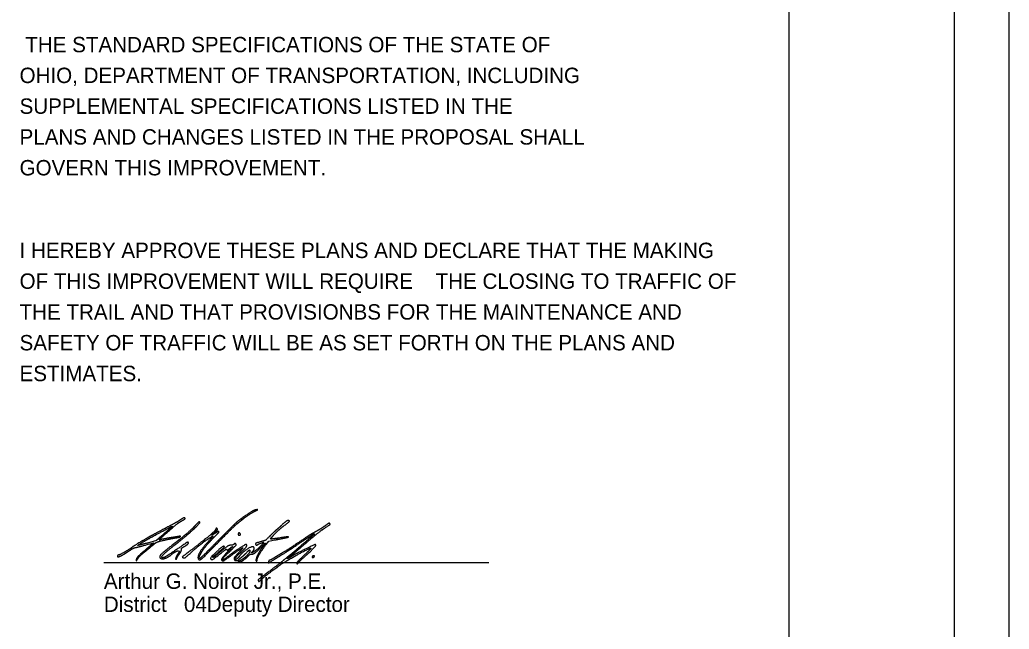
# Model space of a CAD drawing. Extents: x 0 to 34, y 0 to 22.
# Drawn here: x 25 to 34, y 5.54 to 11.09 of the extents above; entities that cross this region are included whole.
import ezdxf

# ---------------------------------------------------------------- set-up
doc = ezdxf.new("R2010")
doc.units = 0
for name, color, linetype in [('GM_X_Adjacent_County', 7, 'Continuous'), ('GM_X_County', 7, 'Continuous'), ('GM_X_Section', 7, 'Continuous'), ('GM_X_Township', 7, 'Continuous')]:
    doc.layers.add(name, color=color, linetype=linetype)

msp = doc.modelspace()

# ---------------------------------------------------------------- linework, layer by layer
at = {"layer": 'GM_X_Adjacent_County'}
for points in [[(26.2935, 6.3944), (26.2439, 6.3503), (26.1624, 6.3283)], [(26.7672, 6.4101), (26.7469, 6.3986), (26.7751, 6.4249)], [(27.2428, 6.3143), (27.2658, 6.3447), (27.3219, 6.3561)], [(27.2968, 6.3642), (27.2808, 6.3622), (27.2948, 6.38)], [(26.4457, 6.2567), (26.4563, 6.2553), (26.4396, 6.2295)]]:
    msp.add_lwpolyline(points, dxfattribs=at)
for points in [[(27.1637, 6.6317), (27.1424, 6.6325), (27.0858, 6.6008), (27.0143, 6.5481)], [(27.0362, 6.5502), (27.0535, 6.5648), (27.1287, 6.6126), (27.1491, 6.6219)], [(27.1491, 6.6219), (27.1608, 6.6272), (27.1673, 6.6316), (27.1637, 6.6317)], [(26.1849, 6.3732), (26.2619, 6.416), (26.3873, 6.4819), (26.3889, 6.4803)], [(26.4616, 6.5381), (26.4443, 6.5265), (26.3934, 6.4978), (26.3483, 6.4743)], [(26.3555, 6.4361), (26.4202, 6.4925), (26.4521, 6.5174), (26.4779, 6.5316)], [(26.3889, 6.4803), (26.3895, 6.4797), (26.3794, 6.4701), (26.3665, 6.4589)], [(26.4991, 6.557), (26.4955, 6.5583), (26.48, 6.5505), (26.4616, 6.5381)], [(26.4779, 6.5316), (26.5032, 6.5455), (26.5095, 6.553), (26.4991, 6.557)], [(26.6012, 6.4909), (26.5759, 6.4639), (26.5201, 6.4125), (26.4915, 6.3901)], [(26.5144, 6.3932), (26.5522, 6.4244), (26.639, 6.5083), (26.639, 6.5137)], [(26.639, 6.5137), (26.639, 6.5245), (26.6243, 6.5156), (26.6012, 6.4909)], [(27.0143, 6.5481), (26.976, 6.5198), (26.9355, 6.4815), (26.8059, 6.3505)], [(26.8219, 6.3499), (26.8944, 6.424), (26.9629, 6.4916), (26.974, 6.5002)], [(26.974, 6.5002), (26.9963, 6.5176), (27.0233, 6.5393), (27.0362, 6.5502)], [(27.2948, 6.38), (27.3196, 6.4115), (27.3688, 6.4583), (27.4102, 6.4897)], [(27.3779, 6.4851), (27.3645, 6.4722), (27.3471, 6.4567), (27.3393, 6.4505)], [(27.4477, 6.5326), (27.4397, 6.5356), (27.409, 6.5148), (27.3779, 6.4851)], [(27.4102, 6.4897), (27.4521, 6.5214), (27.4583, 6.5285), (27.4477, 6.5326)], [(27.8004, 6.4999), (27.7709, 6.4782), (27.7197, 6.4454), (27.6918, 6.4304)], [(27.7791, 6.4668), (27.822, 6.495), (27.8271, 6.5), (27.8202, 6.5068)], [(27.8202, 6.5068), (27.817, 6.51), (27.8115, 6.5081), (27.8004, 6.4999)], [(26.3483, 6.4743), (26.2723, 6.4348), (26.1933, 6.3924), (26.1789, 6.3836)], [(26.2735, 6.3566), (26.265, 6.3538), (26.3006, 6.3884), (26.3555, 6.4361)], [(26.3665, 6.4589), (26.3535, 6.4477), (26.3207, 6.4187), (26.2935, 6.3944)], [(26.3947, 6.2975), (26.4337, 6.3274), (26.4613, 6.3495), (26.5144, 6.3932)], [(26.4573, 6.3902), (26.4531, 6.3889), (26.4312, 6.3851), (26.4088, 6.3818)], [(26.4631, 6.3873), (26.4643, 6.3909), (26.4624, 6.3918), (26.4573, 6.3902)], [(26.4915, 6.3901), (26.4832, 6.3836), (26.4775, 6.3765), (26.4789, 6.3742)], [(26.5571, 6.2398), (26.6082, 6.2867), (26.7482, 6.3917), (26.7596, 6.3917)], [(26.7835, 6.4538), (26.7782, 6.4396), (26.6843, 6.3583), (26.5896, 6.2859)], [(26.7596, 6.3917), (26.7608, 6.3917), (26.7487, 6.3775), (26.7327, 6.3602)], [(26.766, 6.3771), (26.7924, 6.4037), (26.814, 6.4271), (26.814, 6.429)], [(26.794, 6.427), (26.7905, 6.4241), (26.7784, 6.4164), (26.7672, 6.4101)], [(26.7751, 6.4249), (26.7927, 6.4413), (26.8021, 6.4531), (26.8003, 6.4561)], [(26.8003, 6.4561), (26.7958, 6.4633), (26.7865, 6.462), (26.7835, 6.4538)], [(26.814, 6.429), (26.814, 6.4343), (26.8012, 6.4331), (26.794, 6.427)], [(27.0042, 6.415), (26.9968, 6.4224), (26.9891, 6.4187), (26.9891, 6.4078)], [(26.9891, 6.4078), (26.9891, 6.4027), (26.9919, 6.3999), (26.997, 6.3999)], [(26.997, 6.3999), (27.008, 6.3999), (27.0117, 6.4076), (27.0042, 6.415)], [(27.2802, 6.3955), (27.2363, 6.3526), (27.2348, 6.3516), (27.2038, 6.343)], [(27.3393, 6.4505), (27.3314, 6.4443), (27.3049, 6.4195), (27.2802, 6.3955)], [(27.5001, 6.2952), (27.6063, 6.3677), (27.6813, 6.4151), (27.6813, 6.4098)], [(27.6918, 6.4304), (27.652, 6.409), (27.6219, 6.3902), (27.5611, 6.3489)], [(27.6701, 6.3984), (27.664, 6.3936), (27.625, 6.3604), (27.5835, 6.3246)], [(27.6161, 6.3382), (27.6704, 6.3852), (27.7467, 6.4454), (27.7791, 6.4668)], [(27.6813, 6.4098), (27.6813, 6.4084), (27.6762, 6.4032), (27.6701, 6.3984)], [(26.0929, 6.3335), (26.0415, 6.302), (26.034, 6.2971), (26.0178, 6.2847)], [(26.0485, 6.2859), (26.0527, 6.2859), (26.09, 6.295), (26.1313, 6.3062)], [(26.0761, 6.3062), (26.0716, 6.3062), (26.138, 6.3471), (26.1849, 6.3732)], [(26.1624, 6.3283), (26.1176, 6.3162), (26.0788, 6.3062), (26.0761, 6.3062)], [(26.1159, 6.347), (26.1153, 6.347), (26.1049, 6.3409), (26.0929, 6.3335)], [(26.1789, 6.3836), (26.1619, 6.3732), (26.1169, 6.347), (26.1159, 6.347)], [(26.1313, 6.3062), (26.212, 6.3281), (26.2224, 6.33), (26.2094, 6.3202)], [(26.1931, 6.307), (26.1887, 6.3032), (26.1627, 6.2813), (26.1355, 6.2584)], [(26.1896, 6.2902), (26.2095, 6.3072), (26.2312, 6.325), (26.2379, 6.3298)], [(26.2094, 6.3202), (26.205, 6.3168), (26.1976, 6.3109), (26.1931, 6.307)], [(26.2379, 6.3298), (26.2498, 6.3384), (26.3549, 6.3641), (26.43, 6.3767)], [(26.4088, 6.3818), (26.3654, 6.3753), (26.2852, 6.3604), (26.2735, 6.3566)], [(26.411, 6.3256), (26.3062, 6.2453), (26.2639, 6.1993), (26.2847, 6.1882)], [(26.512, 6.327), (26.4934, 6.3126), (26.3394, 6.2096), (26.3267, 6.203)], [(26.4535, 6.3588), (26.4424, 6.35), (26.4233, 6.3351), (26.411, 6.3256)], [(26.43, 6.3767), (26.448, 6.3798), (26.4621, 6.3843), (26.4631, 6.3873)], [(26.4776, 6.3725), (26.4755, 6.3738), (26.4646, 6.3677), (26.4535, 6.3588)], [(26.4789, 6.3742), (26.4803, 6.372), (26.4797, 6.3712), (26.4776, 6.3725)], [(26.4975, 6.2966), (26.5115, 6.3051), (26.5252, 6.3142), (26.528, 6.317)], [(26.528, 6.317), (26.5406, 6.3293), (26.5265, 6.3382), (26.512, 6.327)], [(26.7327, 6.3602), (26.6736, 6.2963), (26.6227, 6.2199), (26.6227, 6.1952)], [(26.6375, 6.176), (26.6479, 6.176), (26.6934, 6.2189), (26.8219, 6.3499)], [(26.8059, 6.3505), (26.7174, 6.2611), (26.6429, 6.188), (26.6402, 6.1881)], [(26.6445, 6.2237), (26.6642, 6.2627), (26.7099, 6.3205), (26.766, 6.3771)], [(26.9248, 6.3085), (26.9042, 6.308), (26.8727, 6.287), (26.792, 6.2197)], [(27.0416, 6.3062), (26.9857, 6.2713), (26.9325, 6.2354), (26.9059, 6.2146)], [(26.9207, 6.2609), (26.9628, 6.3014), (26.9721, 6.3123), (26.9684, 6.3169)], [(26.9476, 6.3157), (26.9434, 6.3119), (26.9332, 6.3086), (26.9248, 6.3085)], [(26.9684, 6.3169), (26.9622, 6.3243), (26.9568, 6.324), (26.9476, 6.3157)], [(27.0279, 6.2577), (27.0513, 6.2792), (27.0663, 6.2979), (27.0664, 6.3054)], [(27.0664, 6.3054), (27.0665, 6.3146), (27.0558, 6.315), (27.0416, 6.3062)], [(27.1067, 6.2255), (27.1215, 6.224), (27.1614, 6.2536), (27.2067, 6.2997)], [(27.22, 6.3332), (27.2229, 6.3304), (27.1522, 6.2617), (27.1357, 6.2513)], [(27.2038, 6.343), (27.158, 6.3304), (27.1436, 6.3237), (27.1464, 6.3164)], [(27.1464, 6.3164), (27.1491, 6.3095), (27.1605, 6.3083), (27.1665, 6.3143)], [(27.2211, 6.3042), (27.1878, 6.2663), (27.1399, 6.1637), (27.1555, 6.1637)], [(27.1601, 6.172), (27.1601, 6.1896), (27.1984, 6.2555), (27.2428, 6.3143)], [(27.1665, 6.3143), (27.1713, 6.319), (27.2178, 6.3355), (27.22, 6.3332)], [(27.2067, 6.2997), (27.2267, 6.3201), (27.2397, 6.3313), (27.2356, 6.3246)], [(27.2356, 6.3246), (27.2316, 6.3178), (27.225, 6.3087), (27.2211, 6.3042)], [(27.3555, 6.3729), (27.332, 6.3692), (27.3056, 6.3653), (27.2968, 6.3642)], [(27.3219, 6.3561), (27.3527, 6.3624), (27.3931, 6.3704), (27.4115, 6.374)], [(27.4451, 6.3834), (27.4451, 6.3864), (27.4284, 6.3844), (27.3555, 6.3729)], [(27.5611, 6.3489), (27.4726, 6.2887), (27.4534, 6.2764), (27.3942, 6.2412)], [(27.4115, 6.374), (27.43, 6.3776), (27.4451, 6.3819), (27.4451, 6.3834)], [(27.5835, 6.3246), (27.5148, 6.2652), (27.4611, 6.2197), (27.4451, 6.2072)], [(27.5632, 6.2929), (27.5867, 6.3129), (27.6105, 6.3333), (27.6161, 6.3382)], [(27.5774, 6.1906), (27.6181, 6.2255), (27.6935, 6.3004), (27.6935, 6.3058)], [(27.6935, 6.3058), (27.6935, 6.3166), (27.6796, 6.3118), (27.605, 6.2754)], [(25.9062, 6.2207), (25.8993, 6.2207), (25.8898, 6.2132), (25.8898, 6.2077)], [(25.8898, 6.2077), (25.8898, 6.2012), (25.9094, 6.2047), (25.928, 6.2146)], [(26.0178, 6.2847), (25.9986, 6.27), (25.9126, 6.2207), (25.9062, 6.2207)], [(25.928, 6.2146), (25.9385, 6.2201), (25.9681, 6.2385), (25.9939, 6.2553)], [(25.9939, 6.2553), (26.0198, 6.2721), (26.0443, 6.2859), (26.0485, 6.2859)], [(26.1355, 6.2584), (26.0901, 6.2202), (26.0608, 6.1868), (26.0608, 6.1732)], [(26.0751, 6.1851), (26.0873, 6.2038), (26.1049, 6.2214), (26.1346, 6.2447)], [(26.1346, 6.2447), (26.145, 6.2528), (26.1697, 6.2733), (26.1896, 6.2902)], [(26.2929, 6.2014), (26.2929, 6.2092), (26.3511, 6.2641), (26.3947, 6.2975)], [(26.3033, 6.1841), (26.3158, 6.1841), (26.3572, 6.2041), (26.3784, 6.2204)], [(26.3784, 6.2204), (26.4089, 6.2439), (26.435, 6.258), (26.4457, 6.2567)], [(26.4396, 6.2295), (26.4304, 6.2152), (26.4217, 6.1981), (26.4203, 6.1913)], [(26.4307, 6.1905), (26.4315, 6.1948), (26.4383, 6.2068), (26.4457, 6.2172)], [(26.4457, 6.2172), (26.4642, 6.2431), (26.472, 6.2592), (26.472, 6.2711)], [(26.472, 6.2711), (26.472, 6.2792), (26.4773, 6.2844), (26.4975, 6.2966)], [(26.5896, 6.2859), (26.4843, 6.2054), (26.4772, 6.1988), (26.4901, 6.1938)], [(26.4901, 6.1938), (26.4993, 6.1903), (26.5138, 6.2002), (26.5571, 6.2398)], [(26.6402, 6.1881), (26.63, 6.1883), (26.631, 6.1969), (26.6445, 6.2237)], [(26.8524, 6.2981), (26.8452, 6.2981), (26.7368, 6.1968), (26.7367, 6.19)], [(26.7414, 6.1811), (26.7486, 6.1738), (26.7703, 6.1869), (26.8285, 6.2332)], [(26.7595, 6.1964), (26.7548, 6.1966), (26.7562, 6.1979), (26.8194, 6.2532)], [(26.792, 6.2197), (26.7766, 6.2069), (26.7619, 6.1964), (26.7595, 6.1964)], [(26.8194, 6.2532), (26.8574, 6.2864), (26.866, 6.2981), (26.8524, 6.2981)], [(26.8285, 6.2332), (26.8745, 6.27), (26.8804, 6.2736), (26.8849, 6.2674)], [(26.8479, 6.1774), (26.8434, 6.1819), (26.8683, 6.2105), (26.9207, 6.2609)], [(26.9059, 6.2146), (26.8679, 6.185), (26.8511, 6.1742), (26.8479, 6.1774)], [(26.9158, 6.2727), (26.8944, 6.2517), (26.8713, 6.2267), (26.8518, 6.2033)], [(26.8849, 6.2674), (26.8896, 6.261), (26.8912, 6.2615), (26.9039, 6.2726)], [(26.9039, 6.2726), (26.9302, 6.2954), (26.9391, 6.2955), (26.9158, 6.2727)], [(26.9091, 6.2041), (26.9529, 6.2364), (27.0298, 6.2873), (27.0318, 6.2853)], [(26.9948, 6.2431), (26.9572, 6.2032), (26.9503, 6.1923), (26.9532, 6.1773)], [(26.9606, 6.186), (26.9606, 6.1916), (26.9891, 6.2219), (27.0279, 6.2577)], [(27.0318, 6.2853), (27.0325, 6.2845), (27.0159, 6.2655), (26.9948, 6.2431)], [(27.1258, 6.2924), (27.1098, 6.2986), (27.021, 6.239), (26.9984, 6.2069)], [(27.0166, 6.1973), (27.0272, 6.2054), (27.0467, 6.2232), (27.0599, 6.2368)], [(27.095, 6.2531), (27.095, 6.2436), (27.0485, 6.1946), (27.0242, 6.1784)], [(27.0599, 6.2368), (27.0849, 6.2625), (27.095, 6.2672), (27.095, 6.2531)], [(27.0782, 6.2084), (27.0917, 6.2222), (27.0986, 6.2264), (27.1067, 6.2255)], [(27.1357, 6.2513), (27.1143, 6.2378), (27.1071, 6.2383), (27.1207, 6.2525)], [(27.1207, 6.2525), (27.1328, 6.2652), (27.1358, 6.2886), (27.1258, 6.2924)], [(27.3942, 6.2412), (27.3629, 6.2226), (27.3276, 6.2011), (27.3159, 6.1935)], [(27.3535, 6.2026), (27.3762, 6.2152), (27.4642, 6.2708), (27.5001, 6.2952)], [(27.4573, 6.1818), (27.539, 6.2304), (27.6546, 6.2888), (27.6491, 6.2785)], [(27.4586, 6.2049), (27.4684, 6.2125), (27.4863, 6.2272), (27.4984, 6.2376)], [(27.605, 6.2754), (27.5308, 6.2391), (27.5016, 6.2234), (27.46, 6.1974)], [(27.4984, 6.2376), (27.5105, 6.248), (27.5397, 6.2729), (27.5632, 6.2929)], [(27.5918, 6.2207), (27.5405, 6.1724), (27.5202, 6.1482), (27.5233, 6.139)], [(27.6491, 6.2785), (27.6468, 6.2742), (27.621, 6.2482), (27.5918, 6.2207)], [(27.6725, 6.2119), (27.6672, 6.2112), (27.6624, 6.2072), (27.6616, 6.2031)], [(27.6806, 6.2058), (27.6817, 6.2116), (27.6798, 6.213), (27.6725, 6.2119)], [(26.0608, 6.1732), (26.0608, 6.1648), (26.063, 6.1666), (26.0751, 6.1851)], [(26.2847, 6.1882), (26.2889, 6.1859), (26.2973, 6.1841), (26.3033, 6.1841)], [(26.3267, 6.203), (26.3113, 6.1951), (26.2929, 6.1942), (26.2929, 6.2014)], [(26.4203, 6.1913), (26.4184, 6.1818), (26.4192, 6.1794), (26.4236, 6.1808)], [(26.4236, 6.1808), (26.4267, 6.1819), (26.4299, 6.1862), (26.4307, 6.1905)], [(26.6227, 6.1952), (26.6227, 6.19), (26.6249, 6.1835), (26.6276, 6.1808)], [(26.6276, 6.1808), (26.6303, 6.1782), (26.6347, 6.176), (26.6375, 6.176)], [(26.7367, 6.19), (26.7367, 6.1877), (26.7388, 6.1836), (26.7414, 6.1811)], [(26.8518, 6.2033), (26.84, 6.1891), (26.8357, 6.1721), (26.8428, 6.1677)], [(26.8428, 6.1677), (26.85, 6.1632), (26.8644, 6.1711), (26.9091, 6.2041)], [(26.9532, 6.1773), (26.9543, 6.1718), (26.9584, 6.1699), (26.9688, 6.1699)], [(26.9984, 6.2069), (26.9855, 6.1886), (26.9606, 6.1749), (26.9606, 6.186)], [(26.9688, 6.1699), (26.9769, 6.17), (26.9859, 6.167), (26.99, 6.1628)], [(27.0242, 6.1784), (26.9924, 6.1572), (26.9858, 6.1736), (27.0166, 6.1973)], [(26.99, 6.1628), (26.994, 6.1588), (26.9998, 6.1556), (27.0029, 6.1556)], [(27.0029, 6.1556), (27.0119, 6.1556), (27.0587, 6.1884), (27.0782, 6.2084)], [(27.1555, 6.1637), (27.158, 6.1637), (27.1601, 6.1675), (27.1601, 6.172)], [(27.3922, 6.1636), (27.3899, 6.1611), (27.3077, 6.0982), (27.2375, 6.0454)], [(27.2635, 6.158), (27.2588, 6.1457), (27.2742, 6.1513), (27.31, 6.1748)], [(27.266, 6.1661), (27.266, 6.1651), (27.2649, 6.1615), (27.2635, 6.158)], [(27.2803, 6.1737), (27.2724, 6.1704), (27.266, 6.167), (27.266, 6.1661)], [(27.3159, 6.1935), (27.3042, 6.1859), (27.2881, 6.177), (27.2803, 6.1737)], [(27.31, 6.1748), (27.3294, 6.1877), (27.349, 6.2002), (27.3535, 6.2026)], [(27.3413, 6.1081), (27.3525, 6.1165), (27.368, 6.1283), (27.3758, 6.1343)], [(27.3758, 6.1343), (27.3836, 6.1403), (27.3918, 6.1455), (27.3941, 6.1459)], [(27.4451, 6.2072), (27.4327, 6.1976), (27.3942, 6.1658), (27.3922, 6.1636)], [(27.3941, 6.1459), (27.3964, 6.1463), (27.4249, 6.1624), (27.4573, 6.1818)], [(27.46, 6.1974), (27.4382, 6.1837), (27.4373, 6.1883), (27.4586, 6.2049)], [(27.5233, 6.139), (27.5241, 6.1365), (27.5293, 6.1408), (27.5348, 6.1485)], [(27.5348, 6.1485), (27.5403, 6.1562), (27.5595, 6.1751), (27.5774, 6.1906)], [(27.6616, 6.2031), (27.6605, 6.1973), (27.6623, 6.196), (27.6697, 6.197)], [(27.6697, 6.197), (27.6749, 6.1977), (27.6798, 6.2017), (27.6806, 6.2058)], [(27.2375, 6.0454), (27.177, 5.9998), (27.1666, 5.9905), (27.17, 5.985)], [(27.2005, 5.9978), (27.2251, 6.0205), (27.2326, 6.0264), (27.3413, 6.1081)], [(27.17, 5.985), (27.1748, 5.9773), (27.181, 5.9799), (27.2005, 5.9978)]]:
    msp.add_open_spline(points, degree=2, dxfattribs=at)
at = {"layer": 'GM_X_County'}
msp.add_line((32, 0.5), (32, 21.5), dxfattribs=at)
msp.add_lwpolyline([(1.5, 21.5), (33.5, 21.5), (33.5, 0.5), (1.5, 0.5)], close=True, dxfattribs=at)
at = {"layer": 'GM_X_Section'}
msp.add_lwpolyline([(0, 0), (34, 0), (34, 22), (0, 22)], close=True, dxfattribs=at)
at = {"layer": 'GM_X_Township'}
msp.add_line((25.7668, 6.1512), (29.2668, 6.1512), dxfattribs=at)

# ---------------------------------------------------------------- texts
at = {"layer": 'GM_X_Adjacent_County'}
for s, p in [(' THE STANDARD SPECIFICATIONS OF THE STATE OF', (25, 10.7925)), ('OHIO, DEPARTMENT OF TRANSPORTATION, INCLUDING', (25, 10.5125)), ('SUPPLEMENTAL SPECIFICATIONS LISTED IN THE', (25, 10.2325)), ('PLANS AND CHANGES LISTED IN THE PROPOSAL SHALL', (25, 9.9525)), ('GOVERN THIS IMPROVEMENT.', (25, 9.6725)), ('I HEREBY APPROVE THESE PLANS AND DECLARE THAT THE MAKING ', (25, 8.9205)), ('OF THIS IMPROVEMENT WILL REQUIRE', (25, 8.6405)), (' THE CLOSING TO TRAFFIC OF ', (28.7317, 8.6405)), ('THE TRAIL AND THAT PROVISIONBS FOR THE MAINTENANCE AND ', (25, 8.3605)), ('SAFETY OF TRAFFIC WILL BE AS SET FORTH ON THE PLANS AND ', (25, 8.0805)), ('ESTIMATES.', (25, 7.8005)), ('Arthur G. Noirot Jr., P.E.', (25.7668, 5.9112)), ('District       Deputy Director', (25.7668, 5.7012)), ('              04', (25.7668, 5.7012))]:
    msp.add_text(s, height=0.14, dxfattribs=at).set_placement(p)

doc.saveas('drawing.dxf')
